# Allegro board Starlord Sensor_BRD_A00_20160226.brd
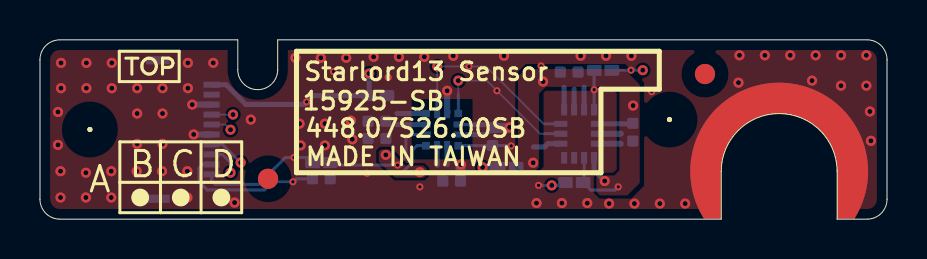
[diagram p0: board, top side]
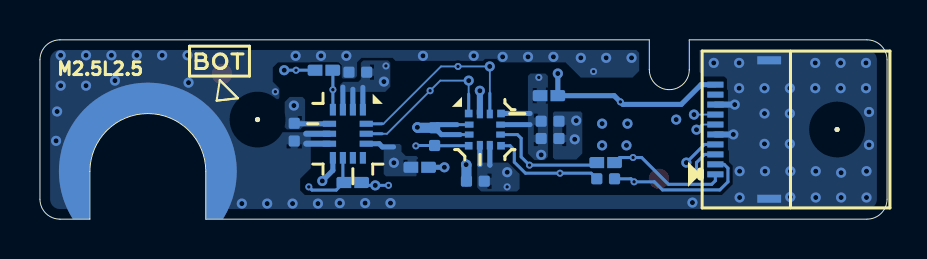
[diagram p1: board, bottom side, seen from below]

Outline 42.4 x 9 mm; copper layers: TOP, L2GND, L3, L4, L5VCC, L6, L7GND, BOTTOM. Coordinates in mm from the lower left corner of the outline.
Outline path: 0,8 0,1 arc(0.29,0.29) 1,0 34.1,0 34.1,2.4 arc(37,5.3) 39.9,2.4 39.9,0 41.4,0 arc(42.11,0.29) 42.4,1 42.4,8 arc(42.11,8.71) 41.4,9 11.9,9 11.9,7.5 arc(10.9,6.5) 9.9,7.5 9.9,9 1,9 arc(0.29,8.71) 0,8

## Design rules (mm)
constraint set DEFAULT: min track width 0.127, pair gap 0.102
net group I2C-MW: nets SENSOR_I2C_SCL SENSOR_I2C_SDA
net group POWER_10-MW: nets 3D3V_S0
net group SENSOR-MW: nets GSEN_INT1 GSEN_INT1_BD_U GSEN_INT2 GSEN_INT2_BD_U GYRO_DRDY GYRO_DRDY_BD_R GYRO_DRDY_C1 GYRO_INT GYRO_INT_R

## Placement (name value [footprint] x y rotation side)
C309  SCD1U10V2KX-5GP  [C402H22]  26.49 7.38 270 bottom
C310  SCD1U10V2KX-5GP  [C402H22]  29.67 4.37 180 bottom
C311  SCD1U10V2KX-5GP  [C402H22]  22.65 4.14 0 bottom
C312  SCD1U10V2KX-5GP  [C402H22]  20.61 1.91 270 bottom
C313  SCD1U10V2KX-5GP  [C402H22]  16.87 4.91 90 bottom
C314  SC1U10V2KX-L1-GP  [C402H22]  16.87 4.05 90 bottom
NOREF  -  [unnamed]  2.5 4.5 0 top
NOREF#2  -  [#2]  5.47 7.66 0 top
NOREF#3  -  [unnamed]  31.51 5 0 top
NOREF#4  *  [unnamed]  33.29 7.28 0 top
NOREF#5  -  [#2]  -15.1 -17.1 0 top
NOREF#6  -  [#2]  -15.1 -17.1 0 top
NOREF#7  -  [#2]  7.81 2.61 0 top
NOREF#8  -  [#2]  -15.1 -17.1 0 top
NOREF#9  *  [unnamed]  11.42 2.03 0 top
NOREF#10  -  [#2]  33.41 7.92 180 bottom
R301  0R2J-2-GP  [R402H16]  14.08 2.03 270 bottom
R302  -  [0R0402-PAD]  23.39 2.6 270 bottom
R309  -  [0R0402-PAD]  28.19 7.48 90 bottom
R310  -  [0R0402-PAD]  26.74 1.84 270 bottom
R312  -  [0R0402-PAD]  14.08 2.84 270 bottom
R313  -  [0R0402-PAD]  16.92 6.2 270 bottom
SBD1  KYO-CON10-1-GP  [04-6809-610210846]  5.9 4.5 90 bottom
U303  LIS3MDLTR-GP  [LGA12G2H40]  20.13 4.49 90 bottom
U304  LSM6DS3USTR-GP  [LGA14G2530-1H34]  26.99 4.29 270 bottom

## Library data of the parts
C309-C313 = C402H22: tolerance: 78.10423.2FL
C314 = C402H22: tolerance: 78.10523.L2L
R301 = R402H16: tolerance: 63.R0034.1DL
R302 R309 R310 R312 R313 = 0R0402-PAD: tolerance: ZZ.R0402.ZZZ
SBD1 = 04-6809-610210846: tolerance: 020.K0159.0010
U303 = LGA12G2H40: tolerance: 074.LIS3M.00B0
U304 = LGA14G2530-1H34: tolerance: 074.LSM63.0AB0

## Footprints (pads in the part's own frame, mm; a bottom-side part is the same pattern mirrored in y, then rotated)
0R0402-PAD
  custom 0.14x0.14 smd: 1(0,0.445) 2(0,-0.445)
04-6809-610210846
  rect 0.305x0.813 smd: 1(-2.25,2.693) 2(-1.75,2.693) 3(-1.25,2.693) 4(-0.75,2.693) 5(-0.25,2.693) 6(0.25,2.693) 7(0.75,2.693) 8(1.25,2.693) 9(1.75,2.693) 10(2.25,2.693)
  rect 0.406x1.194 smd: 11(-3.475,0) 12(3.475,0)
C402H22
  custom 0.14x0.14 smd: 1(0,0.445) 2(0,-0.445)
LGA12G2H40
  rect 0.381x0.381 smd: 1(0.809,0.809) 4(-0.809,0.809) 7(-0.809,-0.809) 10(0.809,-0.809)
  rect 0.305x0.432 smd: 2(0.25,0.784) 3(-0.25,0.784) 8(-0.25,-0.784) 9(0.25,-0.784)
  rect 0.432x0.305 smd: 5(-0.784,0.25) 6(-0.784,-0.25) 11(0.784,-0.25) 12(0.784,0.25)
LGA14G2530-1H34
  rect 0.584x0.305 smd: 1(-1.208,0.75) 2(-1.208,0.25) 3(-1.208,-0.25) 4(-1.208,-0.75) 8(1.208,-0.75) 9(1.208,-0.25) 10(1.208,0.25) 11(1.208,0.75)
  rect 0.305x0.66 smd: 5(-0.5,-0.92) 6(0,-0.92) 7(0.5,-0.92) 12(0.5,0.92) 13(0,0.92) 14(-0.5,0.92)
R402H16
  custom 0.14x0.14 smd: 1(0,0.445) 2(0,-0.445)
unnamed
  round 0.254 hole 2.184 unplated: (0,0)

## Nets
GND: C309.2 C310.2 C311.2 C312.2 C313.2 C314.2 SBD1.5 SBD1.8 SBD1.11 SBD1.12 U303.2 U303.3 U303.12 U304.6 U304.7
3D3V_GSEN_S0: C309.1 C310.1 R302.2 U304.1 U304.2 U304.3 U304.5 U304.8 U304.12
3D3V_GYRO_S0: C312.1 C313.1 C314.1 R313.2 U303.5 U303.6 U303.9 U303.10
3D3V_S0: R302.1 R313.1 SBD1.10
GSEN_INT1: R309.1 SBD1.4
GSEN_INT1_BD_U: R309.2 U304.4
GSEN_INT2: R310.1 SBD1.3
GSEN_INT2_BD_U: R310.2 U304.9
GYRO_DRDY: R312.1 SBD1.1
GYRO_DRDY_BD_R: R312.2 U303.8
GYRO_DRDY_C1: C311.1 U303.4
GYRO_INT: R301.1 SBD1.2
GYRO_INT_R: R301.2 U303.7
SENSOR_I2C_SCL: SBD1.6 U303.1 U304.13
SENSOR_I2C_SDA: SBD1.7 U303.11 U304.14

Pads without a net: SBD1 9; U304 10 11

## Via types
v1: diameter 0.356, hole 0.178, TOP to BOTTOM, 17 vias
v2: diameter 0.508, hole 0.254, TOP to BOTTOM, 87 vias

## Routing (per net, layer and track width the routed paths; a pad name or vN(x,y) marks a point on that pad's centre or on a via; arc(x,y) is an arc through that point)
GND: length 10.7
  BOTTOM w0.152: 21.37,4.24 U303.3 ; 21.53,4.74 U303.2
  BOTTOM w0.254: 21.37,4.24 22.3,4.24 C311.2 22.49,4.74 21.53,4.74
  BOTTOM w0.305: v2(7.62,5.75) 7.62,5.75 SBD1.8 ; U304.6 29.07,4.29 ; U304.7 29.07,3.79 ; SBD1.5 7.7,4.25 v2(7.69,4.25) ; v2(20.38,6.44) U303.12
  BOTTOM w0.508: C312.2 21.05,2.72 v2(21.07,2.74) ; v2(23.51,4.61) 23.49,4.59 C311.2
  vias: v1(14.69,7.41) v1(30.62,6.39) v2(0.9,5.38) v2(0.9,3.73) v2(1.03,2.41) v2(1.03,1.09) v2(1.05,7.84) v2(1.05,6.57) v2(2.32,7.84) v2(2.32,6.57) v2(2.3,2.33) v2(2.3,1.09) v2(3.59,7.84) v2(3.59,6.57) v2(3.57,2.41) v2(3.57,1.09) v2(4.84,2.41) v2(4.84,1.11) v2(4.86,6.57) v2(4.86,5.3) v2(4.86,3.78) v2(6.13,6.57) v2(6.13,5.3) v2(6.13,3.78) v2(6.11,2.41) v2(7.4,7.84) v2(7.4,6.57) v2(7.38,2.41) v2(7.38,1.09) v2(8.67,7.84) v2(9.74,0.83) v2(10.55,5) v2(12.79,8.1) v2(12.99,4.79) v2(13.04,3.7) v2(14.06,8.1) v2(14.26,4.79) v2(14.26,3.7) v2(15.33,8.1) v2(15.56,4.95) v2(15.63,4.01) v2(16.7,8.15) v2(17.97,8.15) v2(19.24,8.15) v2(20.69,8.2) v2(23.23,8.2) v2(24.85,0.81) v2(26.12,0.81) v2(27.06,8.2) v2(27.39,0.81) v2(28.33,8.2) v2(28.49,0.78) v2(29.6,8.2) v2(29.76,0.78) v2(31.03,0.78) v2(32.3,0.78) v2(35.01,8.22) v2(34.96,6.85) v2(36.28,8.22) v2(37.55,8.22) v2(38.65,6.95) v2(38.82,8.22) v2(40.09,8.22) v2(40.09,6.7) v2(41.36,8.22) v2(41.36,6.7) v2(41.54,5.4) v2(41.59,3.93)
3D3V_GSEN_S0: length 7.9
  BOTTOM w0.254: v2(28.27,1.92) 27.74,2.45 U304.8 ; U304.2 26.74,6.52 ; U304.3 27.24,6.63 ; U304.12 25.42,3.79 25.26,3.63 24.7,3.63 ; C310.1 29.65,4.79 U304.5 ; U304.1 26.24,6.61
  vias: v1(25.08,7.69) v2(24.69,2.83) v2(25.18,6.9) v2(29.69,5.7)
3D3V_GYRO_S0: length 4.9
  BOTTOM w0.254: 19.88,2.71 19.88,2.72 U303.6 ; U303.5 20.38,2.74 20.38,2.74 ; U303.9 17.87,4.74 ; U303.10 17.87,5.3
  vias: v1(17.43,7.11) v1(19.02,1.62) v2(17.31,3.23) v2(19.01,2.36)
3D3V_S0: length 21.4
  L3 w0.254: v2(22.16,2.6) 21.35,1.8 17.36,1.8 16.48,2.68 v2(16.48,7.31)
  BOTTOM w0.254: v2(16.48,7.31) R313.1 13.66,6.2 v1(13.35,5.89) 13.22,5.76 10.3,5.76 9.31,6.75 SBD1.10 ; R302.1 v2(22.16,2.6)
GSEN_INT1: length 28.3
  L3 w0.152: v2(10.05,2.84) 11.52,1.37 24.09,1.37 25.21,2.48 27.95,2.48 28.97,3.5 28.97,6.27 v2(30.17,7.48)
  BOTTOM w0.152: v2(10.05,2.84) 9.14,3.75 SBD1.4 ; v2(30.17,7.48) v1(29.58,7.48) R309.1
GSEN_INT1_BD_U: length 2
  BOTTOM w0.152: U304.4 v1(27.74,6.5) 27.74,7.47 R309.2
GSEN_INT2: length 19.9
  L3 w0.152: v2(25.62,1.7) v1(24.96,1.7) 24.3,1.04 11.09,1.04 9.79,2.33 v2(9.54,2.33)
  BOTTOM w0.152: SBD1.3 9.13,3.25 9.54,2.84 v2(9.54,2.33) ; v1(24.96,1.7) v2(25.62,1.7) 26.15,1.7 R310.1
GSEN_INT2_BD_U: length 3.2
  BOTTOM w0.152: v1(28.94,1.62) 28.78,1.46 27.57,1.46 R310.2 27.24,1.89 U304.9
GYRO_DRDY: length 6.1
  BOTTOM w0.152: SBD1.1 8.59,1.93 8.78,1.75 10.93,1.75 12.28,3.09 v1(12.71,3.09) 13.39,3.09 R312.1
GYRO_DRDY_BD_R: length 6.1
  BOTTOM w0.152: R312.2 14.66,2.71 v1(17.9,2.71) 18.31,3.13 18.31,4.06 18.5,4.24 U303.8
GYRO_DRDY_C1: length 2.7
  BOTTOM w0.152: v1(23.58,3.68) 23.56,3.7 C311.1 22.63,3.68 U303.4
GYRO_INT: length 7.5
  BOTTOM w0.152: SBD1.2 8.15,2.75 7.96,2.56 7.96,1.87 8.37,1.47 11.24,1.47 11.65,1.87 v1(12.66,1.87) 12.81,2.03 R301.1
GYRO_INT_R: length 5.8
  BOTTOM w0.152: R301.2 14.81,2.31 v1(16.37,2.31) 18.1,2.31 18.66,2.86 18.66,3.47 18.87,3.68 U303.7
SENSOR_I2C_SCL: length 21.4
  L6 w0.102: v2(9.54,4.49) 11.32,4.49 13.07,6.24 17.28,6.24 17.99,6.95 v2(20.94,6.95)
  BOTTOM w0.089: 20.94,6.27 20.94,6.95 v2(20.94,6.95) 22.36,6.95 v1(22.87,6.45) 25.03,4.29 25.27,4.29 ; v2(9.54,4.49) 9.28,4.75 SBD1.6
  BOTTOM w0.152: 20.94,6.27 U303.1 ; U304.13 25.27,4.29
SENSOR_I2C_SDA: length 22.1
  L6 w0.102: v2(19.89,7.66) 17.79,7.66 16.95,6.83 12.89,6.83 11.57,5.51 9.92,5.51 v2(9.66,5.25)
  BOTTOM w0.089: SBD1.7 v2(9.66,5.25) ; 19.88,6.32 19.88,7.66 v2(19.89,7.66) v1(21.48,7.66) 22.33,7.66 25.21,4.79 25.29,4.79
  BOTTOM w0.152: 19.88,6.32 U303.11 ; U304.14 25.29,4.79

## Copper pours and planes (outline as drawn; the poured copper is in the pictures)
GND on TOP: 1,0.51 0.65,0.65 0.51,1 0.51,8 0.65,8.35 1,8.49 9.39,8.49 9.39,7.5 10.9,5.99 12.41,7.5 12.41,8.49 41.4,8.49 41.75,8.35 41.89,8 41.89,1 41.75,0.65 41.4,0.51 40.41,0.51 40.41,2.4 37,5.81 33.59,2.4 33.59,0.51 ; 1 cut-out
GND on BOTTOM: 1,0.51 0.65,0.65 0.51,1 0.51,8 0.65,8.35 1,8.49 9.39,8.49 9.39,7.5 9.4,7.4 9.16,7.16 8.14,7.16 8.01,7.03 8.01,6.52 7.96,6.47 7.96,3.47 7.91,3.42 7.91,2.86 7.72,2.67 7.72,1.76 8.27,1.21 29.15,1.21 29.38,1.44 29.38,2.03 28.84,2.56 28.84,4.26 28.94,4.36 30.24,4.36 30.42,4.54 30.42,6.57 30.75,6.9 30.75,7.61 30.49,7.87 27.44,7.87 27.29,7.72 27.29,7.11 27.24,7.06 26.66,7.06 26.53,7.18 26.53,7.87 26.3,8.1 24.75,8.1 24.6,7.94 20.22,7.94 20.12,8.05 19.55,8.05 19.38,7.87 16.09,7.87 15.33,7.11 12.74,7.11 12.41,7.44 12.41,8.35 12.55,8.49 41.4,8.49 41.75,8.35 41.89,8 41.89,1 41.75,0.65 41.4,0.51 40.41,0.51 40.41,2.4 37,5.81 33.59,2.4 33.59,0.63 33.47,0.51 ; 2 cut-outs
GND on BOTTOM: 15.56,2.99 15.25,3.3 15.25,5.32 15.34,5.4 16.65,5.4 16.72,5.33 16.72,3.09 16.62,2.99 ; 2 cut-outs
GND on L2GND, L5VCC, L7GND: 1,0.51 0.65,0.65 0.51,1 0.51,8 0.65,8.35 1,8.49 9.39,8.49 9.39,7.5 10.9,5.99 12.41,7.5 12.41,8.49 41.4,8.49 41.75,8.35 41.89,8 41.89,1 41.75,0.65 41.4,0.51 40.41,0.51 40.41,2.4 37,5.81 33.59,2.4 33.59,0.51
GND on L3, L4, L6: 1,0.51 0.65,0.65 0.51,1 0.51,8 0.65,8.35 1,8.49 9.39,8.49 9.39,7.5 10.9,5.99 12.41,7.5 12.41,8.49 41.4,8.49 41.75,8.35 41.89,8 41.89,1 41.75,0.65 41.4,0.51 40.41,0.51 40.41,2.4 37,5.81 33.59,2.4 33.59,0.51
3D3V_GSEN_S0 on TOP: 25.32,6.64 24.98,6.3 24.98,2.61 24.81,2.45 24.07,2.45 23.92,2.6 23.92,7.15 24.31,7.53 29.24,7.53 30.02,6.75 30.02,1.82 29.39,1.19 28.03,1.19 27.85,1.37 27.85,2.07 27.98,2.2 28.75,2.2 29,2.45 29,6.39 28.75,6.64
3D3V_GSEN_S0 on BOTTOM: 29.36,4.51 29.13,4.74 29.13,6.01 29.26,6.13 29.89,6.13 30.15,5.88 30.15,4.61 30.04,4.51 ; 1 cut-out
3D3V_GSEN_S0 on BOTTOM: 25.12,6.39 24.86,6.64 24.86,7.85 24.98,7.97 26.21,7.97 26.34,7.84 26.34,7.02 26.46,6.9 27.23,6.9 27.38,6.74 27.38,6.42 27.35,6.39 ; 2 cut-outs
3D3V_GSEN_S0 on BOTTOM: 23.58,2.15 23.48,2.25 23.48,3.09 23.56,3.17 24.09,3.17 24.31,3.38 24.31,3.69 24.39,3.77 25.02,3.77 25.19,3.59 25.19,2.26 25.08,2.15 ; 1 cut-out
3D3V_GYRO_S0 on TOP: 19.22,2.08 17.78,2.08 17.69,2.17 17.68,2.17 16.96,2.89 16.96,3.4 17.06,3.5 17.49,3.5 18.3,2.69 19.19,2.69 19.37,2.51 19.37,2.23
3D3V_GYRO_S0 on BOTTOM: 18.53,1.39 18.39,1.53 18.39,2.27 18.96,2.84 20.38,2.84 20.52,2.71 20.52,1.59 20.31,1.39 ; 2 cut-outs
3D3V_GYRO_S0 on BOTTOM: 17.14,2.97 16.98,3.13 16.98,7.19 17.1,7.31 17.85,7.31 17.98,7.19 17.98,3.3 17.64,2.97 ; 5 cut-outs

Small or netless copper shapes (teardrops, artwork), in the pictures only: 1 on TOP, 1 on BOTTOM

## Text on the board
Ref Des/Silkscreen Bottom: M2.5L2.5
Ref Des/Silkscreen Top: 15925-SB | Starlord13 Sensor | 448.07S26.00SB | MADE IN TAIWAN
User.27: ByImpedance:100.0@_REF_L1=("nil(L1)")|_REF_L6=("4.0/10.0(L6)")|Type="DP"|_REF_L4=("4.0/6.5(L4)")|_REF_L3=("4.0/6.5(L3)" "4.0/10.0(L3)")|imp="100.0"|_REF_L8=("nil(L8)") | ByImpedance:33.0@_REF_L1=("8.0(L1)")|_REF_L6=("9.0(L6)")|Type="SE"|_REF_L4=("11.0(L4)")|_REF_L3=("11.0(L3)" "9.0(L3)")|imp="33.0"|_REF_L8=("8.0(L8)") | ByImpedance:35.0@_REF_L1=("7.5(L1)")|_REF_L6=("8.5(L6)")|Type="SE"|_REF_L4=("10.0(L4)")|_REF_L3=("10.0(L3)" "8.5(L3)")|imp="35.0"|_REF_L8=("7.5(L8)") | ByImpedance:37.5@_REF_L1=("6.5(L1)")|_REF_L6=("7.5(L6)")|Type="SE"|_REF_L4=("9.0(L4)")|_REF_L3=("7.5(L3)" "9.0(L3)")|imp="37.5"|_REF_L8=("6.5(L8)") | ByImpedance:40.0@_REF_L1=("6.0(L1)")|_REF_L6=("6.5(L6)")|Type="SE"|_REF_L4=("8.0(L4)")|_REF_L3=("6.5(L3)" "8.0(L3)")|imp="40.0"|_REF_L8=("6.0(L8)") | ByImpedance:45.0@_REF_L1=("4.5(L1)")|_REF_L6=("5.0(L6)")|Type="SE"|_REF_L4=("6.5(L4)")|_REF_L3=("6.5(L3)" "5.0(L3)")|imp="45.0"|_REF_L8=("4.5(L8)") | ByImpedance:50.0@_REF_L1=("3.5(L1)")|_REF_L6=("4.0(L6)")|Type="SE"|_REF_L4=("5.0(L4)")|_REF_L3=("4.0(L3)" "5.0(L3)")|imp="50.0"|_REF_L8=("3.5(L8)") | ByImpedance:55.0@_REF_L1=("nil(L1)")|_REF_L6=("nil(L6)")|Type="SE"|_REF_L4=("4.0(L4)")|_REF_L3=("4.0(L3)")|imp="55.0"|_REF_L8=("nil(L8)") | ByImpedance:60.0@_REF_L1=("7.5/4.0(L1)")|_REF_L6=("9.5/4.5(L6)")|Type="DP"|_REF_L4=("10.5/4.5(L4)")|_REF_L3=("10.5/4.5(L3)" "9.5/4.5(L3)")|imp="60.0"|_REF_L8=("7.5/4.0(L8)") | ByImpedance:63.0@_REF_L1=("7.0/4.5(L1)")|_REF_L6=("8.5/4.0(L6)")|Type="DP"|_REF_L4=("9.5/4.0(L4)")|_REF_L3=("8.5/4.0(L3)" "9.5/4.0(L3)")|imp="63.0"|_REF_L8=("7.0/4.5(L8)") | ByImpedance:70.0@_REF_L1=("6.0/5.0(L1)")|_REF_L6=("7.0/5.0(L6)")|Type="DP"|_REF_L4=("8.5/5.0(L4)")|_REF_L3=("7.0/5.0(L3)" "8.5/5.0(L3)")|imp="70.0"|_REF_L8=("6.0/5.0(L8)") | ByImpedance:72.0@_REF_L1=("5.5/4.5(L1)")|_REF_L6=("6.5/4.5(L6)")|Type="DP"|_REF_L4=("7.5/5.0(L4)")|_REF_L3=("7.5/5.0(L3)" "6.5/4.5(L3)")|imp="72.0"|_REF_L8=("5.5/4.5(L8)") | ByImpedance:75.0@_REF_L1=("5.0/4.5(L1)")|_REF_L6=("6.0/4.5(L6)")|Type="DP"|_REF_L4=("7.0/5.0(L4)")|_REF_L3=("7.0/5.0(L3)" "6.0/4.5(L3)")|imp="75.0"|_REF_L8=("5.0/4.5(L8)") | ByImpedance:80.0@_REF_L1=("4.5/5.0(L1)")|_REF_L6=("5.5/5.0(L6)")|Type="DP"|_REF_L4=("6.0/5.0(L4)")|_REF_L3=("5.5/5.0(L3)" "6.0/5.0(L3)")|imp="80.0"|_REF_L8=("4.5/5.0(L8)") | ByImpedance:83.0@_REF_L1=("3.5/4.0(L1)")|_REF_L6=("5.0/4.0(L6)")|Type="DP"|_REF_L4=("5.5/4.5(L4)")|_REF_L3=("5.5/4.5(L3)" "5.0/4.0(L3)")|imp="83.0"|_REF_L8=("3.5/4.0(L8)") | ByImpedance:85.0@_REF_L1=("4.0/5.0(L1)")|_REF_L6=("5.0/5.5(L6)")|Type="DP"|_REF_L4=("5.5/5.0(L4)")|_REF_L3=("5.5/5.0(L3)" "5.0/5.5(L3)")|imp="85.0"|_REF_L8=("4.0/5.0(L8)") | ByImpedance:88.0@_REF_L1=("4.0/7.0(L1)")|_REF_L6=("4.0/4.0(L6)")|Type="DP"|_REF_L4=("5.0/5.0(L4)")|_REF_L3=("4.0/4.0(L3)" "5.0/5.0(L3)")|imp="88.0"|_REF_L8=("4.0/7.0(L8)") | ByImpedance:90.0@_REF_L1=("4.0/8.0(L1)" "3.5/6.0(L1)")|_REF_L6=("4.0/4.5(L6)")|Type="DP"|_REF_L4=("5.0/6.0(L4)")|_REF_L3=("5.0/6.0(L3)" "4.0/4.5(L3)")|imp="90.0"|_REF_L8=("4.0/8.0(L8)" "3.5/6.0(L8)") | LayerIndex:nil | Source:8-1.0-16f.xls | artWorks:("_REF_L3" "_REF_L6" "_REF_L4" "_REF_L8" "_REF_L1") | gtImpOutlineUsed:BOARD GEOMETRY/OUTLINE
User.28: Board Accuracy Check,Jan 13 16:14:56 2016,Passed | Dummy-Static-No Shape On Layer Check,Jan 13 16:14:56 2016,Passed | Split Plane Check,Oct 14 15:23:21 2015,Passed
User.30: This gerber is just for your reference to find the DP impedance traces in layer L1. | DP IMPEDANCE TABLE: L1 | * - Denotes that this Impedance | is NOT used | IMP(Ohm) | *60.0 | *63.0 | *70.0 | *72.0 | *75.0 | *80.0 | *83.0 | *85.0 | *88.0 | *90.0 | *100.0 | WIDTH(mils) | 7.5/4.0 | 7.0/4.5 | 6.0/5.0 | 5.5/4.5 | 5.0/4.5 | 4.5/5.0 | 3.5/4.0 | 4.0/5.0 | 4.0/7.0 | 4.0/8.0 | 3.5/6.0 | nil | TYPE | DP
User.32: This gerber is just for your reference to find the SE impedance traces in layer L1. | SE IMPEDANCE TABLE: L1 | * - Denotes that this Impedance | is NOT used | IMP(Ohm) | *33.0 | *35.0 | *37.5 | *40.0 | *45.0 | *50.0 | *55.0 | WIDTH(mils) | 8.0 | 7.5 | 6.5 | 6.0 | 4.5 | 3.5 | nil | TYPE | SE
User.34: This gerber is just for your reference to find the DP impedance traces in layer L3. | DP IMPEDANCE TABLE: L3 | * - Denotes that this Impedance | is NOT used | IMP(Ohm) | *60.0 | *63.0 | *70.0 | *72.0 | *75.0 | *80.0 | *83.0 | *85.0 | *88.0 | *90.0 | *100.0 | WIDTH(mils) | 10.5/4.5 | 9.5/4.5 | 8.5/4.0 | 9.5/4.0 | 7.0/5.0 | 8.5/5.0 | 7.5/5.0 | 6.5/4.5 | 6.0/4.5 | 5.5/5.0 | 6.0/5.0 | 5.5/4.5 | 5.0/4.0 | 5.0/5.5 | 4.0/4.0 | 5.0/5.0 | 5.0/6.0 | 4.0/4.5 | 4.0/6.5 | 4.0/10.0 | TYPE | DP
User.36: This gerber is just for your reference to find the SE impedance traces in layer L3. | SE IMPEDANCE TABLE: L3 | * - Denotes that this Impedance | is NOT used | IMP(Ohm) | *33.0 | *35.0 | *37.5 | *40.0 | *45.0 | *50.0 | *55.0 | WIDTH(mils) | 11.0 | 9.0 | 10.0 | 8.5 | 7.5 | 6.5 | 8.0 | 5.0 | 4.0 | TYPE | SE
User.38: This gerber is just for your reference to find the DP impedance traces in layer L4. | DP IMPEDANCE TABLE: L4 | * - Denotes that this Impedance | is NOT used | IMP(Ohm) | *60.0 | *63.0 | *70.0 | *72.0 | *75.0 | *80.0 | *83.0 | *85.0 | *88.0 | *90.0 | *100.0 | WIDTH(mils) | 10.5/4.5 | 9.5/4.0 | 8.5/5.0 | 7.5/5.0 | 7.0/5.0 | 6.0/5.0 | 5.5/4.5 | 5.5/5.0 | 5.0/5.0 | 5.0/6.0 | 4.0/6.5 | TYPE | DP
User.40: This gerber is just for your reference to find the SE impedance traces in layer L4. | SE IMPEDANCE TABLE: L4 | * - Denotes that this Impedance | is NOT used | IMP(Ohm) | *33.0 | *35.0 | *37.5 | *40.0 | *45.0 | *50.0 | *55.0 | WIDTH(mils) | 11.0 | 10.0 | 9.0 | 8.0 | 6.5 | 5.0 | 4.0 | TYPE | SE
User.42: This gerber is just for your reference to find the DP impedance traces in layer L6. | DP IMPEDANCE TABLE: L6 | * - Denotes that this Impedance | is NOT used | IMP(Ohm) | *60.0 | *63.0 | *70.0 | *72.0 | *75.0 | *80.0 | *83.0 | *85.0 | *88.0 | *90.0 | *100.0 | WIDTH(mils) | 9.5/4.5 | 8.5/4.0 | 7.0/5.0 | 6.5/4.5 | 6.0/4.5 | 5.5/5.0 | 5.0/4.0 | 5.0/5.5 | 4.0/4.0 | 4.0/4.5 | 4.0/10.0 | TYPE | DP
User.44: This gerber is just for your reference to find the SE impedance traces in layer L6. | SE IMPEDANCE TABLE: L6 | * - Denotes that this Impedance | is NOT used | IMP(Ohm) | *33.0 | *35.0 | *37.5 | *40.0 | *45.0 | 50.0 | *55.0 | WIDTH(mils) | 9.0 | 8.5 | 7.5 | 6.5 | 5.0 | 4.0 | nil | TYPE | SE
User.45: Note:Refer to DRILL layer for ELLIPSE drill direction | FIGURE | SIZE | 10.0 | 86.0 | DRILL CHART: TOP to BOTTOM | ALL UNITS ARE IN MILS | PLATED | NON-PLATED | QTY | 87 | 2 | This gerber is just for your reference to find the SE impedance traces in layer L8. | This gerber is just for your reference to find the DP impedance traces in layer L8. | DP IMPEDANCE TABLE: L8 | SE IMPEDANCE TABLE: L8 | * - Denotes that this Impedance | is NOT used | Model | Starlord13 Sensor | IMP(Ohm) | *33.0 | *60.0 | *35.0 | *63.0 | *37.5 | *70.0 | *40.0 | *72.0 | *45.0 | *75.0 | *80.0 | 50.0 | *55.0 | *83.0 | *85.0 | *88.0 | *90.0 | *100.0 | PCB_NO | 15925 | VER. | SB | WIDTH(mils) | 8.0 | 7.5 | 6.5 | 6.0 | 4.5 | 3.5 | nil | 7.5/4.0 | 7.0/4.5 | 6.0/5.0 | 5.5/4.5 | 5.0/4.5 | 4.5/5.0 | 3.5/4.0 | 4.0/5.0 | 4.0/7.0 | 4.0/8.0 | 3.5/6.0 | Layer | DRILL | L1 | L2GND | L3 | L4 | TMASK | TPLACE | TSILK | TSMD | TYPE | SE | DP | Designer | JAZZ_XUE | Date | 01/13/2016 | BMASK | BPLACE | BSILK | BSMD | L5VCC | L6 | L7GND | L8
